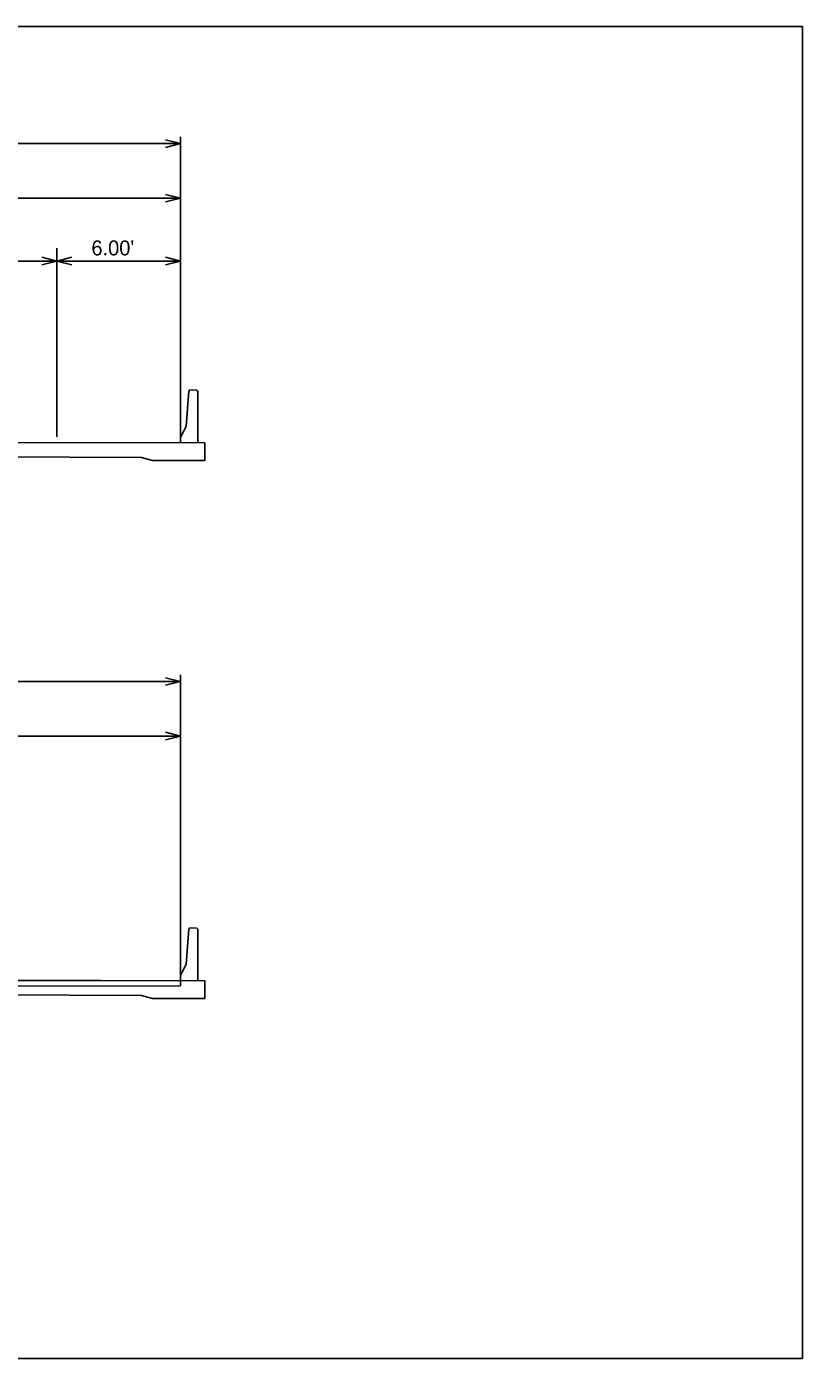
# Model space of a CAD drawing. Extents: x 8410 to 81668, y 7924 to 12712.
# Drawn here: x 12091 to 13268, y 7924 to 9944 of the extents above; entities that cross this region are included whole.
import ezdxf

# ---------------------------------------------------------------- set-up
doc = ezdxf.new("R2010")
doc.units = 0
for name, color, linetype in [('Level 2', 7, 'Continuous'), ('Level 3', 7, 'Continuous'), ('SheetBorder', 7, 'Continuous')]:
    doc.layers.add(name, color=color, linetype=linetype)

msp = doc.modelspace()

# ---------------------------------------------------------------- linework, layer by layer
at = {"layer": 'Level 2'}
for p, q in [((12324.3, 9766.6), (11075.7, 9766.6)), ((12324.3, 9312.7), (12324.3, 9776.7)), ((12324.3, 9683.9), (11637.6, 9683.9)), ((12137, 9321.8), (12137, 9608)), ((12137, 9321.8), (12137, 9608)), ((12137, 9321.8), (12137, 9608)), ((12137, 9321.8), (12137, 9608)), ((12137, 9588.5), (11762.5, 9588.5)), ((12137, 9588.5), (12324.3, 9588.5)), ((12337.1, 9391), (12332.9, 9338)), ((12338.5, 9392.9), (12337.1, 9391)), ((12349.3, 9392.6), (12338.5, 9392.9)), ((12350.7, 9390.7), (12349.3, 9392.6)), ((12350.7, 9312.7), (12350.7, 9390.7)), ((12332.9, 9338), (12324.4, 9320.7)), ((12324.4, 9320.7), (12324.3, 9312.7)), ((12265.5, 9290.3), (11700, 9293.3)), ((12281.8, 9285.9), (12265.5, 9290.3)), ((12324.3, 8950.7), (11075.7, 8950.7)), ((12324.3, 8496.8), (12324.3, 8960.7)), ((12324.3, 8868), (11637.6, 8868)), ((12337.1, 8575.1), (12332.9, 8522)), ((12338.5, 8576.9), (12337.1, 8575.1)), ((12349.3, 8576.7), (12338.5, 8576.9)), ((12350.7, 8574.8), (12349.3, 8576.7)), ((12350.7, 8496.7), (12350.7, 8574.8)), ((12324.4, 8504.7), (12324.3, 8496.8)), ((12332.9, 8522), (12324.4, 8504.7)), ((12265.5, 8474.4), (11700, 8477.3)), ((12281.8, 8469.9), (12265.5, 8474.4))]:
    msp.add_line(p, q, dxfattribs=at)
for points in [[(12301.6, 9772.3), (12324.3, 9766.6), (12301.6, 9760.9)], [(12301.6, 9689.6), (12324.3, 9683.9), (12301.6, 9678.2)], [(12114.3, 9582.8), (12137, 9588.5), (12114.3, 9594.2)], [(12159.7, 9582.8), (12137, 9588.5), (12159.7, 9594.2)], [(12301.6, 9582.8), (12324.3, 9588.5), (12301.6, 9594.2)], [(12361.2, 9312.6), (12361.2, 9285.9), (12281.8, 9285.9)], [(12301.6, 8956.3), (12324.3, 8950.7), (12301.6, 8945)], [(12301.6, 8873.6), (12324.3, 8868), (12301.6, 8862.3)], [(12361.2, 8496.7), (12361.2, 8469.9), (12281.8, 8469.9)]]:
    msp.add_lwpolyline(points, dxfattribs=at)
at = {"layer": 'Level 3'}
for p, q in [((11637.6, 9314.4), (12361.2, 9312.6)), ((11637.6, 8498.4), (12361.2, 8496.7))]:
    msp.add_line(p, q, dxfattribs=at)
msp.add_lwpolyline([(12068, 8497.4), (12324.3, 8496.8), (12324.3, 8489.2), (12065.9, 8488.7)], dxfattribs=at)
at = {"layer": 'SheetBorder'}
msp.add_lwpolyline([(10132.5, 9944), (13267.5, 9944), (13267.5, 7924), (10132.5, 7924)], close=True, dxfattribs=at)

# ---------------------------------------------------------------- texts
at = {"layer": 'Level 2'}
msp.add_text("6.00'", height=22.71, dxfattribs=at).set_placement((12189.4, 9597))

doc.saveas('drawing.dxf')
